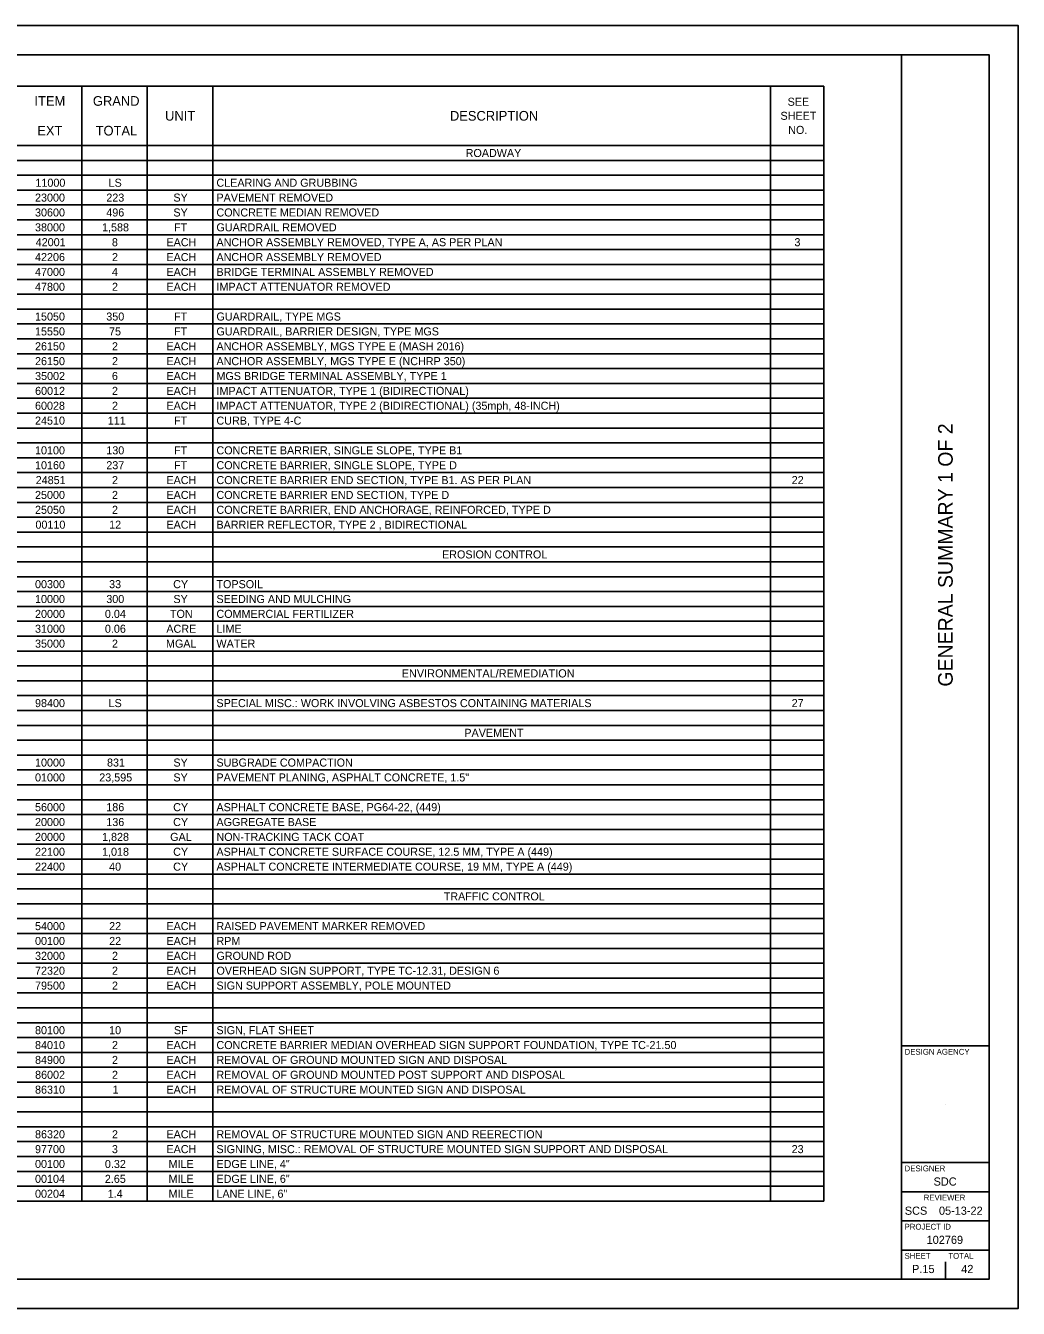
# Model space of a CAD drawing. Extents: x 0 to 34, y 0 to 22.
# Drawn here: x 16.98 to 34, y 0 to 22 of the extents above; entities that cross this region are included whole.
import ezdxf

# ---------------------------------------------------------------- set-up
doc = ezdxf.new("R2010")
doc.units = 0
for name, color, linetype in [('SH_Border', 7, 'Continuous'), ('SH_Cut_Line', 7, 'Continuous'), ('SH_Data', 7, 'Continuous'), ('SH_Text', 7, 'Continuous')]:
    doc.layers.add(name, color=color, linetype=linetype)

msp = doc.modelspace()

# ---------------------------------------------------------------- linework, layer by layer
at = {"layer": 'SH_Border'}
for p, q in [((32, 0.5), (32, 21.5)), ((32, 4.5), (33.5, 4.5)), ((32, 2.5), (33.5, 2.5)), ((32, 2), (33.5, 2)), ((32, 1.5), (33.5, 1.5)), ((32, 1), (33.5, 1))]:
    msp.add_line(p, q, dxfattribs=at)
msp.add_lwpolyline([(1.5, 21.5), (33.5, 21.5), (33.5, 0.5), (1.5, 0.5)], close=True, dxfattribs=at)
at = {"layer": 'SH_Cut_Line'}
msp.add_lwpolyline([(0, 0), (34, 0), (34, 22), (0, 22)], close=True, dxfattribs=at)
at = {"layer": 'SH_Data'}
for p, q in [((32.75, 3.5), (32.75, 3.5)), ((32.375, 0.675), (32.375, 0.675)), ((32.75, 0.5), (32.75, 0.8))]:
    msp.add_line(p, q, dxfattribs=at)
at = {"layer": 'SH_Text'}
for p, q in [((2.884, 20.964), (30.664, 20.964)), ((17.944, 20.964), (17.944, 1.839)), ((19.069, 20.964), (19.069, 1.839)), ((20.194, 20.964), (20.194, 1.839)), ((29.749, 20.964), (29.749, 1.839)), ((30.664, 20.964), (30.664, 1.839)), ((2.884, 19.944), (30.664, 19.944)), ((2.884, 19.689), (30.664, 19.689)), ((2.884, 19.434), (30.664, 19.434)), ((2.884, 19.179), (30.664, 19.179)), ((2.884, 18.924), (30.664, 18.924)), ((2.884, 18.669), (30.664, 18.669)), ((2.884, 18.414), (30.664, 18.414)), ((2.884, 18.159), (30.664, 18.159)), ((2.884, 17.904), (30.664, 17.904)), ((2.884, 17.649), (30.664, 17.649)), ((2.884, 17.394), (30.664, 17.394)), ((2.884, 17.139), (30.664, 17.139)), ((2.884, 16.884), (30.664, 16.884)), ((2.884, 16.629), (30.664, 16.629)), ((2.884, 16.374), (30.664, 16.374)), ((2.884, 16.119), (30.664, 16.119)), ((2.884, 15.864), (30.664, 15.864)), ((2.884, 15.609), (30.664, 15.609)), ((2.884, 15.354), (30.664, 15.354)), ((2.884, 15.099), (30.664, 15.099)), ((2.884, 14.844), (30.664, 14.844)), ((2.884, 14.589), (30.664, 14.589)), ((2.884, 14.334), (30.664, 14.334)), ((2.884, 14.079), (30.664, 14.079)), ((2.884, 13.824), (30.664, 13.824)), ((2.884, 13.569), (30.664, 13.569)), ((2.884, 13.314), (30.664, 13.314)), ((2.884, 13.059), (30.664, 13.059)), ((2.884, 12.804), (30.664, 12.804)), ((2.884, 12.549), (30.664, 12.549)), ((2.884, 12.294), (30.664, 12.294)), ((2.884, 12.039), (30.664, 12.039)), ((2.884, 11.784), (30.664, 11.784)), ((2.884, 11.529), (30.664, 11.529)), ((2.884, 11.274), (30.664, 11.274)), ((2.884, 11.019), (30.664, 11.019)), ((2.884, 10.764), (30.664, 10.764)), ((2.884, 10.509), (30.664, 10.509)), ((2.884, 10.254), (30.664, 10.254)), ((2.884, 9.999), (30.664, 9.999)), ((2.884, 9.744), (30.664, 9.744)), ((2.884, 9.489), (30.664, 9.489)), ((2.884, 9.234), (30.664, 9.234)), ((2.884, 8.979), (30.664, 8.979)), ((2.884, 8.724), (30.664, 8.724)), ((2.884, 8.469), (30.664, 8.469)), ((2.884, 8.214), (30.664, 8.214)), ((2.884, 7.959), (30.664, 7.959)), ((2.884, 7.704), (30.664, 7.704)), ((2.884, 7.449), (30.664, 7.449)), ((2.884, 7.194), (30.664, 7.194)), ((2.884, 6.939), (30.664, 6.939)), ((2.884, 6.684), (30.664, 6.684)), ((2.884, 6.429), (30.664, 6.429)), ((2.884, 6.174), (30.664, 6.174)), ((2.884, 5.919), (30.664, 5.919)), ((2.884, 5.664), (30.664, 5.664)), ((2.884, 5.409), (30.664, 5.409)), ((2.884, 5.154), (30.664, 5.154)), ((2.884, 4.899), (30.664, 4.899)), ((2.884, 4.644), (30.664, 4.644)), ((2.884, 4.389), (30.664, 4.389)), ((2.884, 4.134), (30.664, 4.134)), ((2.884, 3.879), (30.664, 3.879)), ((2.884, 3.624), (30.664, 3.624)), ((2.884, 3.369), (30.664, 3.369)), ((2.884, 3.114), (30.664, 3.114)), ((2.884, 2.859), (30.664, 2.859)), ((2.884, 2.604), (30.664, 2.604)), ((2.884, 2.349), (30.664, 2.349)), ((2.884, 2.094), (30.664, 2.094)), ((2.884, 1.839), (30.664, 1.839))]:
    msp.add_line(p, q, dxfattribs=at)

# ---------------------------------------------------------------- texts
at = {"layer": 'SH_Data'}
msp.add_text('GENERAL SUMMARY 1 OF 2', height=0.25, rotation=90, dxfattribs=at).set_placement((32.875, 10.664))
for s, height, p in [('DESIGN AGENCY', 0.1, (32.05, 4.35)), ('DESIGNER', 0.1, (32.05, 2.35)), ('SDC', 0.14, (32.547, 2.105)), ('REVIEWER', 0.1, (32.378, 1.85)), ('SCS', 0.14, (32.054, 1.605)), ('05-13-22', 0.14, (32.639, 1.605)), ('PROJECT ID', 0.1, (32.05, 1.35)), ('102769', 0.14, (32.428, 1.105)), ('SHEET', 0.1, (32.05, 0.85)), ('TOTAL', 0.1, (32.8, 0.85)), ('P.15', 0.14, (32.178, 0.605)), ('42', 0.14, (33.021, 0.605))]:
    msp.add_text(s, height=height, dxfattribs=at).set_placement(p)
at = {"layer": 'SH_Text'}
for s, height, p in [('ITEM', 0.1656, (17.134, 20.626)), ('GRAND', 0.1656, (18.136, 20.626)), ('SEE ', 0.138, (30.045, 20.626)), ('UNIT', 0.1656, (19.373, 20.371)), ('DESCRIPTION', 0.1656, (24.256, 20.371)), ('SHEET ', 0.138, (29.923, 20.385)), ('EXT', 0.1656, (17.183, 20.116)), ('TOTAL', 0.1656, (18.183, 20.116)), ('NO.', 0.138, (30.055, 20.143)), ('ROADWAY', 0.138, (24.526, 19.747)), ('11000', 0.138, (17.151, 19.237)), ('LS', 0.138, (18.405, 19.237)), ('CLEARING AND GRUBBING', 0.138, (20.254, 19.237)), ('23000', 0.138, (17.144, 18.982)), ('223', 0.138, (18.366, 18.982)), ('SY', 0.138, (19.516, 18.982)), ('PAVEMENT REMOVED', 0.138, (20.254, 18.982)), ('30600', 0.138, (17.144, 18.727)), ('496', 0.138, (18.366, 18.727)), ('SY', 0.138, (19.516, 18.727)), ('CONCRETE MEDIAN REMOVED', 0.138, (20.254, 18.727)), ('38000', 0.138, (17.144, 18.472)), ('1,588', 0.138, (18.293, 18.472)), ('FT', 0.138, (19.527, 18.472)), ('GUARDRAIL REMOVED', 0.138, (20.254, 18.472)), ('42001', 0.138, (17.156, 18.217)), ('8', 0.138, (18.462, 18.217)), ('EACH', 0.138, (19.397, 18.217)), ('ANCHOR ASSEMBLY REMOVED, TYPE A, AS PER PLAN', 0.138, (20.254, 18.217)), ('3', 0.138, (30.162, 18.217)), ('42206', 0.138, (17.144, 17.962)), ('2', 0.138, (18.463, 17.962)), ('EACH', 0.138, (19.397, 17.962)), ('ANCHOR ASSEMBLY REMOVED', 0.138, (20.254, 17.962)), ('47000', 0.138, (17.144, 17.707)), ('4', 0.138, (18.462, 17.707)), ('EACH', 0.138, (19.397, 17.707)), ('BRIDGE TERMINAL ASSEMBLY REMOVED', 0.138, (20.254, 17.707)), ('47800', 0.138, (17.144, 17.452)), ('2', 0.138, (18.463, 17.452)), ('EACH', 0.138, (19.397, 17.452)), ('IMPACT ATTENUATOR REMOVED', 0.138, (20.254, 17.452)), ('15050', 0.138, (17.144, 16.942)), ('350', 0.138, (18.366, 16.942)), ('FT', 0.138, (19.527, 16.942)), ('GUARDRAIL, TYPE MGS', 0.138, (20.254, 16.942)), ('15550', 0.138, (17.144, 16.687)), ('75', 0.138, (18.413, 16.687)), ('FT', 0.138, (19.527, 16.687)), ('GUARDRAIL, BARRIER DESIGN, TYPE MGS', 0.138, (20.254, 16.687)), ('26150', 0.138, (17.144, 16.432)), ('2', 0.138, (18.463, 16.432)), ('EACH', 0.138, (19.397, 16.432)), ('ANCHOR ASSEMBLY, MGS TYPE E (MASH 2016)', 0.138, (20.254, 16.432)), ('26150', 0.138, (17.144, 16.177)), ('2', 0.138, (18.463, 16.177)), ('EACH', 0.138, (19.397, 16.177)), ('ANCHOR ASSEMBLY, MGS TYPE E (NCHRP 350)', 0.138, (20.254, 16.177)), ('35002', 0.138, (17.145, 15.922)), ('6', 0.138, (18.462, 15.922)), ('EACH', 0.138, (19.397, 15.922)), ('MGS BRIDGE TERMINAL ASSEMBLY, TYPE 1', 0.138, (20.254, 15.922)), ('60012', 0.138, (17.145, 15.667)), ('2', 0.138, (18.463, 15.667)), ('EACH', 0.138, (19.397, 15.667)), ('IMPACT ATTENUATOR, TYPE 1 (BIDIRECTIONAL)', 0.138, (20.254, 15.667)), ('60028', 0.138, (17.144, 15.412)), ('2', 0.138, (18.463, 15.412)), ('EACH', 0.138, (19.397, 15.412)), ('IMPACT ATTENUATOR, TYPE 2 (BIDIRECTIONAL) (35mph, 48-INCH)', 0.138, (20.254, 15.412)), ('24510', 0.138, (17.144, 15.157)), ('111', 0.138, (18.391, 15.157)), ('FT', 0.138, (19.527, 15.157)), ('CURB, TYPE 4-C', 0.138, (20.254, 15.157)), ('10100', 0.138, (17.144, 14.647)), ('130', 0.138, (18.366, 14.647)), ('FT', 0.138, (19.527, 14.647)), ('CONCRETE BARRIER, SINGLE SLOPE, TYPE B1', 0.138, (20.254, 14.647)), ('10160', 0.138, (17.144, 14.392)), ('237', 0.138, (18.366, 14.392)), ('FT', 0.138, (19.527, 14.392)), ('CONCRETE BARRIER, SINGLE SLOPE, TYPE D', 0.138, (20.254, 14.392)), ('24851', 0.138, (17.156, 14.137)), ('2', 0.138, (18.463, 14.137)), ('EACH', 0.138, (19.397, 14.137)), ('CONCRETE BARRIER END SECTION, TYPE B1. AS PER PLAN', 0.138, (20.254, 14.137)), ('22', 0.138, (30.115, 14.137)), ('25000', 0.138, (17.144, 13.882)), ('2', 0.138, (18.463, 13.882)), ('EACH', 0.138, (19.397, 13.882)), ('CONCRETE BARRIER END SECTION, TYPE D', 0.138, (20.254, 13.882)), ('25050', 0.138, (17.144, 13.627)), ('2', 0.138, (18.463, 13.627)), ('EACH', 0.138, (19.397, 13.627)), ('CONCRETE BARRIER, END ANCHORAGE, REINFORCED, TYPE D', 0.138, (20.254, 13.627)), ('00110', 0.138, (17.151, 13.372)), ('12', 0.138, (18.415, 13.372)), ('EACH', 0.138, (19.397, 13.372)), ('BARRIER REFLECTOR, TYPE 2 , BIDIRECTIONAL', 0.138, (20.254, 13.372)), ('EROSION CONTROL', 0.138, (24.121, 12.862)), ('00300', 0.138, (17.144, 12.352)), ('33', 0.138, (18.414, 12.352)), ('CY', 0.138, (19.512, 12.352)), ('TOPSOIL', 0.138, (20.254, 12.352)), ('10000', 0.138, (17.144, 12.097)), ('300', 0.138, (18.366, 12.097)), ('SY', 0.138, (19.516, 12.097)), ('SEEDING AND MULCHING', 0.138, (20.254, 12.097)), ('20000', 0.138, (17.144, 11.842)), ('0.04', 0.138, (18.342, 11.842)), ('TON', 0.138, (19.457, 11.842)), ('COMMERCIAL FERTILIZER', 0.138, (20.254, 11.842)), ('31000', 0.138, (17.144, 11.587)), ('0.06', 0.138, (18.342, 11.587)), ('ACRE', 0.138, (19.395, 11.587)), ('LIME', 0.138, (20.254, 11.587)), ('35000', 0.138, (17.144, 11.332)), ('2', 0.138, (18.463, 11.332)), ('MGAL', 0.138, (19.389, 11.332)), ('WATER', 0.138, (20.254, 11.332)), ('ENVIRONMENTAL/REMEDIATION', 0.14, (23.429, 10.821)), ('98400', 0.138, (17.144, 10.312)), ('LS', 0.138, (18.405, 10.312)), ('SPECIAL MISC.: WORK INVOLVING ASBESTOS CONTAINING MATERIALS', 0.138, (20.254, 10.312)), ('27', 0.138, (30.114, 10.312)), ('PAVEMENT', 0.138, (24.504, 9.802)), ('10000', 0.138, (17.144, 9.292)), ('831', 0.138, (18.378, 9.292)), ('SY', 0.138, (19.516, 9.292)), ('SUBGRADE COMPACTION', 0.138, (20.254, 9.292)), ('01000', 0.138, (17.144, 9.037)), ('23,595', 0.138, (18.245, 9.037)), ('SY', 0.138, (19.516, 9.037)), ('PAVEMENT PLANING, ASPHALT CONCRETE, 1.5"', 0.138, (20.254, 9.037)), ('56000', 0.138, (17.144, 8.527)), ('186', 0.138, (18.366, 8.527)), ('CY', 0.138, (19.512, 8.527)), ('ASPHALT CONCRETE BASE, PG64-22, (449)', 0.138, (20.254, 8.527)), ('20000', 0.138, (17.144, 8.272)), ('136', 0.138, (18.366, 8.272)), ('CY', 0.138, (19.512, 8.272)), ('AGGREGATE BASE', 0.138, (20.254, 8.272)), ('20000', 0.138, (17.144, 8.017)), ('1,828', 0.138, (18.293, 8.017)), ('GAL', 0.138, (19.461, 8.017)), ('NON-TRACKING TACK COAT', 0.138, (20.254, 8.017)), ('22100', 0.138, (17.144, 7.762)), ('1,018', 0.138, (18.293, 7.762)), ('CY', 0.138, (19.512, 7.762)), ('ASPHALT CONCRETE SURFACE COURSE, 12.5 MM, TYPE A (449)', 0.138, (20.254, 7.762)), ('22400', 0.138, (17.144, 7.507)), ('40', 0.138, (18.414, 7.507)), ('CY', 0.138, (19.512, 7.507)), ('ASPHALT CONCRETE INTERMEDIATE COURSE, 19 MM, TYPE A (449)', 0.138, (20.254, 7.507)), ('TRAFFIC CONTROL', 0.138, (24.15, 6.997)), ('54000', 0.138, (17.144, 6.487)), ('22', 0.138, (18.415, 6.487)), ('EACH', 0.138, (19.397, 6.487)), ('RAISED PAVEMENT MARKER REMOVED', 0.138, (20.254, 6.487)), ('00100', 0.138, (17.144, 6.232)), ('22', 0.138, (18.415, 6.232)), ('EACH', 0.138, (19.397, 6.232)), ('RPM', 0.138, (20.254, 6.232)), ('32000', 0.138, (17.144, 5.977)), ('2', 0.138, (18.463, 5.977)), ('EACH', 0.138, (19.397, 5.977)), ('GROUND ROD', 0.138, (20.254, 5.977)), ('72320', 0.138, (17.144, 5.722)), ('2', 0.138, (18.463, 5.722)), ('EACH', 0.138, (19.397, 5.722)), ('OVERHEAD SIGN SUPPORT, TYPE TC-12.31, DESIGN 6', 0.138, (20.254, 5.722)), ('79500', 0.138, (17.144, 5.467)), ('2', 0.138, (18.463, 5.467)), ('EACH', 0.138, (19.397, 5.467)), ('SIGN SUPPORT ASSEMBLY, POLE MOUNTED', 0.138, (20.254, 5.467)), ('80100', 0.138, (17.144, 4.702)), ('10', 0.138, (18.414, 4.702)), ('SF', 0.138, (19.525, 4.702)), ('SIGN, FLAT SHEET', 0.138, (20.254, 4.702)), ('84010', 0.138, (17.144, 4.447)), ('2', 0.138, (18.463, 4.447)), ('EACH', 0.138, (19.397, 4.447)), ('CONCRETE BARRIER MEDIAN OVERHEAD SIGN SUPPORT FOUNDATION, TYPE TC-21.50', 0.138, (20.254, 4.447)), ('84900', 0.138, (17.144, 4.192)), ('2', 0.138, (18.463, 4.192)), ('EACH', 0.138, (19.397, 4.192)), ('REMOVAL OF GROUND MOUNTED SIGN AND DISPOSAL', 0.138, (20.254, 4.192)), ('86002', 0.138, (17.145, 3.937)), ('2', 0.138, (18.463, 3.937)), ('EACH', 0.138, (19.397, 3.937)), ('REMOVAL OF GROUND MOUNTED POST SUPPORT AND DISPOSAL', 0.138, (20.254, 3.937)), ('86310', 0.138, (17.144, 3.682)), ('1', 0.138, (18.474, 3.682)), ('EACH', 0.138, (19.397, 3.682)), ('REMOVAL OF STRUCTURE MOUNTED SIGN AND DISPOSAL', 0.138, (20.254, 3.682)), ('86320', 0.138, (17.144, 2.917)), ('2', 0.138, (18.463, 2.917)), ('EACH', 0.138, (19.397, 2.917)), ('REMOVAL OF STRUCTURE MOUNTED SIGN AND REERECTION', 0.138, (20.254, 2.917)), ('97700', 0.138, (17.144, 2.662)), ('3', 0.138, (18.462, 2.662)), ('EACH', 0.138, (19.397, 2.662)), ('SIGNING, MISC.: REMOVAL OF STRUCTURE MOUNTED SIGN SUPPORT AND DISPOSAL', 0.138, (20.254, 2.662)), ('23', 0.138, (30.114, 2.662)), ('00100', 0.138, (17.144, 2.407)), ('0.32', 0.138, (18.342, 2.407)), ('MILE', 0.138, (19.434, 2.407)), ('EDGE LINE, 4"', 0.138, (20.254, 2.407)), ('00104', 0.138, (17.144, 2.152)), ('2.65', 0.138, (18.341, 2.152)), ('MILE', 0.138, (19.434, 2.152)), ('EDGE LINE, 6"', 0.138, (20.254, 2.152)), ('00204', 0.138, (17.144, 1.897)), ('1.4', 0.138, (18.39, 1.897)), ('MILE', 0.138, (19.434, 1.897)), ('LANE LINE, 6"', 0.138, (20.254, 1.897))]:
    msp.add_text(s, height=height, dxfattribs=at).set_placement(p)

doc.saveas('drawing.dxf')
